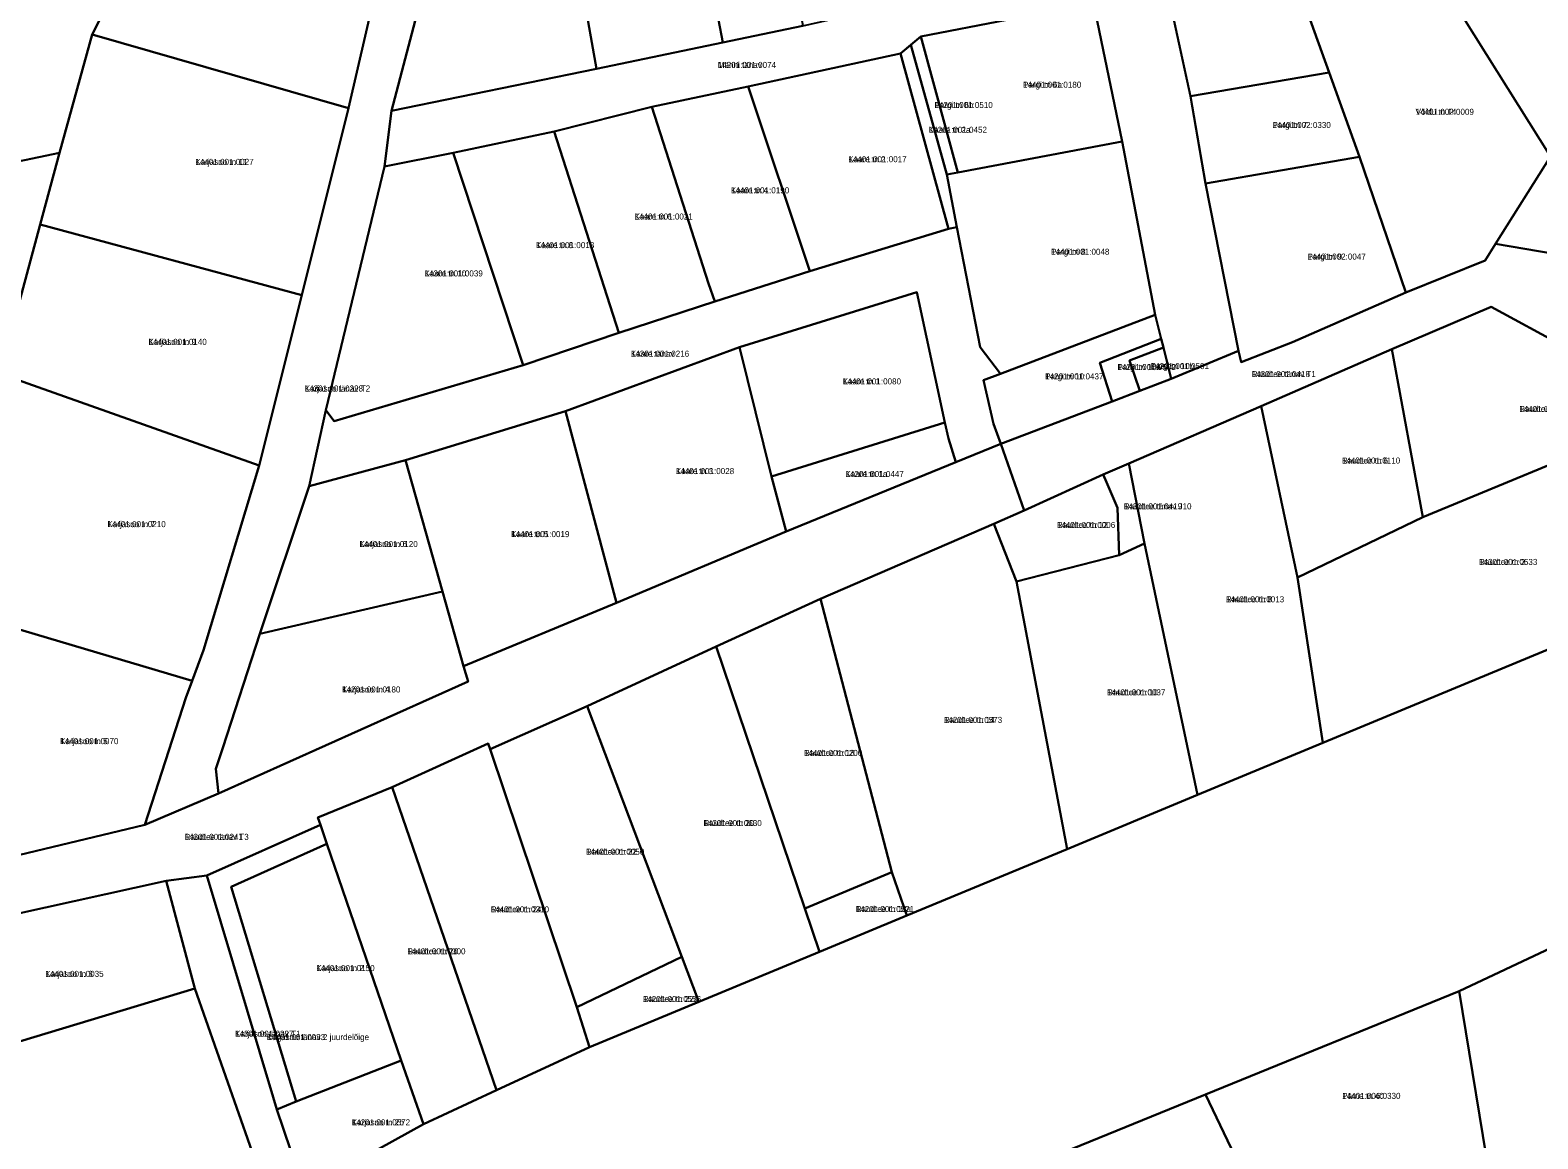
# Model space of a CAD drawing. Extents: x 640657 to 665127, y 6395726 to 6426831.
# Drawn here: x 649552.6 to 649927.6, y 6412104.6 to 6412380.5 of the extents above; entities that cross this region are included whole.
import ezdxf

# ---------------------------------------------------------------- set-up
doc = ezdxf.new("R2010")
doc.units = 0
for name, color, linetype in [('L_AADRESS', 7, 'Continuous'), ('PIIR', 7, 'Continuous'), ('TUNNUS', 7, 'Continuous')]:
    doc.layers.add(name, color=color, linetype=linetype)

msp = doc.modelspace()

# ---------------------------------------------------------------- linework, layer by layer
at = {"layer": 'PIIR'}
for points in [[(649721.82, 6412664.46), (649730.85, 6412627.05), (649736.82, 6412597.75), (649709.02, 6412592.28), (649695.48, 6412590.41), (649677.65, 6412523.96), (649682.12, 6412521.81), (649674.69, 6412506.86), (649582.66, 6412520.01), (649581.58, 6412512.13), (649530.93, 6412519.33), (649565.2, 6412417.51), (649589.31, 6412421.53), (649648.34, 6412432.29), (649646.56, 6412424.89), (649585.01, 6412412.96), (649583.88, 6412410.73), (649568.03, 6412379.35), (649559.94, 6412349.89), (649537.28, 6412345.21)], [(649834.26, 6412395.72), (649841.16, 6412363.98), (649844.88, 6412342.3), (649853.1, 6412300.7), (649836.4, 6412293.7), (649834.44, 6412301.51), (649833.89, 6412303.67), (649832.4, 6412309.6), (649824.2, 6412352.76), (649817.07, 6412387.2)], [(649931.6, 6412324.8), (649917, 6412327.3), (649930.7, 6412349)], [(649952.59, 6412291.69), (649915.96, 6412311.64), (649891.28, 6412301.06), (649858.71, 6412286.93), (649825.86, 6412272.62), (649819.47, 6412269.89), (649799.77, 6412260.97), (649794, 6412277.5), (649821.67, 6412288.07), (649828.58, 6412290.71), (649836.4, 6412293.7), (649853.1, 6412300.7), (649853.8, 6412297.8), (649866.5, 6412302.8), (649894.69, 6412315.18), (649914.43, 6412323.17), (649917, 6412327.3), (649931.6, 6412324.8)], [(649528.9, 6412170.2), (649581.09, 6412182.7), (649599.46, 6412190.55), (649661.5, 6412218.4), (649660.39, 6412222.19), (649698.42, 6412237.99), (649740.6, 6412255.75), (649782.79, 6412272.93), (649794, 6412277.5), (649799.77, 6412260.97), (649792.3, 6412257.59), (649749.16, 6412238.95), (649723.21, 6412227.12), (649691.16, 6412212.27), (649666.97, 6412201.57), (649666.5, 6412202.96), (649642.62, 6412192.14), (649624.18, 6412184.53), (649624.78, 6412182.75), (649596.55, 6412170.1), (649586.4, 6412168.82), (649518.44, 6412153.81)], [(649378.03, 6411957.6), (649560.17, 6412058.25), (649612.7, 6412087.46), (649620.75, 6412091.85), (649650.44, 6412108.25), (649668.58, 6412116.67), (649691.67, 6412127.38), (649718.88, 6412138.69), (649748.94, 6412151.16), (649770.59, 6412160.14), (649810.5, 6412176.7), (649842.91, 6412190.15), (649874.08, 6412203.09), (649950.67, 6412234.89)], [(649966.63, 6412168.97), (649907.99, 6412141.34), (649844.88, 6412115.63), (649769.67, 6412084.97), (649735.24, 6412070.53), (649620.31, 6412010.25), (649606.21, 6412000.36), (649592.49, 6411990.94), (649584.81, 6411986.06), (649559.96, 6411970.08), (649540.51, 6411961.7)]]:
    msp.add_lwpolyline(points, dxfattribs=at)
for points in [[(649744.78, 6412381.55), (649724.89, 6412377.34), (649721.61, 6412394.38), (649719.48, 6412403.99), (649714.06, 6412430.6), (649712.65, 6412437.7), (649712.08, 6412439.62), (649701.28, 6412476.03), (649725.11, 6412479.68), (649733.64, 6412439.3), (649739.77, 6412409.28)], [(649683.72, 6412425.67), (649714.06, 6412430.6), (649719.48, 6412403.99), (649721.61, 6412394.38), (649724.89, 6412377.34), (649693.47, 6412370.82)], [(649599.46, 6412190.55), (649581.09, 6412182.7), (649591.31, 6412214.32), (649592.88, 6412218.54), (649595.75, 6412226.18), (649609.52, 6412272.16), (649620.19, 6412314.5), (649631.74, 6412361.02), (649646.56, 6412424.89), (649660.68, 6412427.63), (649658.51, 6412421.66), (649642.44, 6412360.34), (649640.7, 6412346.54), (649626.17, 6412285.93), (649621.96, 6412267), (649609.71, 6412230.22), (649600.49, 6412201.9), (649598.79, 6412196.69)], [(649568.03, 6412379.35), (649583.88, 6412410.73), (649585.01, 6412412.96), (649646.56, 6412424.89), (649631.74, 6412361.02)], [(649658.51, 6412421.66), (649683.72, 6412425.67), (649693.47, 6412370.82), (649642.44, 6412360.34)], [(649901.45, 6412413.33), (649911.24, 6412406.94), (649952.6, 6412382.3), (649930.7, 6412349), (649895.82, 6412404.71)], [(649930.7, 6412349), (649917, 6412327.3), (649914.43, 6412323.17), (649894.69, 6412315.18), (649883.22, 6412348.91), (649875.65, 6412369.9), (649863.6, 6412403.34), (649892.26, 6412410.82), (649895.82, 6412404.71)], [(649834.26, 6412395.72), (649863.6, 6412403.34), (649875.65, 6412369.9), (649841.15, 6412363.99)], [(649642.44, 6412360.34), (649693.47, 6412370.82), (649724.89, 6412377.34), (649744.78, 6412381.55), (649767.83, 6412386.75), (649791.8, 6412390.86), (649815.85, 6412395.56), (649817.07, 6412387.2), (649774.12, 6412378.85), (649769.02, 6412374.6), (649731.18, 6412366.4), (649707.22, 6412361.37), (649682.96, 6412355.22), (649657.78, 6412349.92), (649640.7, 6412346.54)], [(649774.12, 6412378.85), (649817.07, 6412387.2), (649824.2, 6412352.76), (649783.35, 6412345.04)], [(649620.19, 6412314.5), (649555.12, 6412332.13), (649559.94, 6412349.89), (649568.03, 6412379.35), (649631.74, 6412361.02)], [(649771.66, 6412376.8), (649774.12, 6412378.85), (649783.35, 6412345.04), (649780.6, 6412344.5)], [(649769.02, 6412374.6), (649780.98, 6412330.98), (649746.53, 6412320.48), (649731.18, 6412366.4)], [(649780.98, 6412330.98), (649769.02, 6412374.6), (649771.66, 6412376.8), (649780.6, 6412344.5), (649783.1, 6412331.4)], [(649841.15, 6412363.99), (649875.65, 6412369.9), (649883.22, 6412348.91), (649844.88, 6412342.3)], [(649721.29, 6412317.41), (649707.22, 6412361.37), (649731.18, 6412366.4), (649746.53, 6412320.48), (649722.86, 6412312.91)], [(649682.96, 6412355.22), (649707.22, 6412361.37), (649721.29, 6412317.41), (649722.86, 6412312.91), (649698.99, 6412305.1)], [(649698.99, 6412305.1), (649675.18, 6412297.08), (649657.78, 6412349.92), (649682.96, 6412355.22)], [(649780.6, 6412344.5), (649783.35, 6412345.04), (649824.2, 6412352.76), (649832.4, 6412309.6), (649793.9, 6412294.9), (649788.9, 6412301.6), (649783.1, 6412331.4)], [(649502.69, 6412177.63), (649514.82, 6412175.76), (649522.99, 6412247.98), (649537.28, 6412345.21), (649559.94, 6412349.89), (649555.12, 6412332.13), (649545.05, 6412295.05), (649539.3, 6412261.3), (649537.33, 6412245.72), (649536.16, 6412235.4), (649528.9, 6412170.2), (649501.19, 6412163.13), (649502.36, 6412173.21)], [(649640.7, 6412346.54), (649657.78, 6412349.92), (649675.18, 6412297.08), (649628.25, 6412283.17), (649626.17, 6412285.93)], [(649844.88, 6412342.3), (649883.22, 6412348.91), (649894.69, 6412315.18), (649866.5, 6412302.8), (649853.8, 6412297.8), (649853.1, 6412300.7)], [(649620.19, 6412314.5), (649609.52, 6412272.16), (649552.04, 6412292.57), (649545.05, 6412295.05), (649555.12, 6412332.13)], [(649794, 6412277.5), (649782.79, 6412272.93), (649780.96, 6412278.85), (649780.11, 6412282.79), (649773.12, 6412315.23), (649729.05, 6412301.6), (649685.78, 6412285.67), (649645.99, 6412273.49), (649621.96, 6412267), (649626.17, 6412285.93), (649628.25, 6412283.17), (649675.18, 6412297.08), (649698.99, 6412305.1), (649722.86, 6412312.91), (649746.53, 6412320.48), (649780.98, 6412330.98), (649783.1, 6412331.4), (649788.9, 6412301.6), (649793.9, 6412294.9), (649789.7, 6412293.4), (649792.2, 6412282.5)], [(649780.11, 6412282.79), (649736.93, 6412269.39), (649729.05, 6412301.6), (649773.12, 6412315.23)], [(649891.28, 6412301.06), (649915.96, 6412311.64), (649952.59, 6412291.69), (649951.07, 6412280.86), (649898.94, 6412259.26)], [(649821.67, 6412288.07), (649794, 6412277.5), (649792.2, 6412282.5), (649789.7, 6412293.4), (649793.9, 6412294.9), (649832.4, 6412309.6), (649833.89, 6412303.67), (649818.6, 6412297.67)], [(649828.58, 6412290.71), (649821.67, 6412288.07), (649818.6, 6412297.67), (649833.89, 6412303.67), (649834.44, 6412301.51), (649826.01, 6412298.28)], [(649685.78, 6412285.67), (649729.05, 6412301.6), (649736.93, 6412269.39), (649740.6, 6412255.75), (649698.42, 6412237.99)], [(649836.4, 6412293.7), (649828.58, 6412290.71), (649826.01, 6412298.28), (649834.44, 6412301.51)], [(649858.71, 6412286.93), (649891.28, 6412301.06), (649898.94, 6412259.26), (649867.77, 6412244.26)], [(649537.33, 6412245.72), (649539.3, 6412261.3), (649545.05, 6412295.05), (649552.04, 6412292.57), (649609.52, 6412272.16), (649595.75, 6412226.18), (649592.88, 6412218.54), (649536.16, 6412235.4)], [(649951.07, 6412280.86), (649952.59, 6412291.69), (649954.77, 6412290.58), (649950.67, 6412234.89), (649874.08, 6412203.09), (649867.77, 6412244.26), (649898.94, 6412259.26)], [(649645.99, 6412273.49), (649685.78, 6412285.67), (649698.42, 6412237.99), (649660.39, 6412222.19), (649655.18, 6412240.76)], [(649858.71, 6412286.93), (649867.77, 6412244.26), (649874.08, 6412203.09), (649842.91, 6412190.15), (649829.72, 6412252.69), (649825.86, 6412272.62)], [(649782.79, 6412272.93), (649740.6, 6412255.75), (649736.93, 6412269.39), (649780.11, 6412282.79), (649780.96, 6412278.85)], [(649655.18, 6412240.76), (649609.71, 6412230.22), (649621.96, 6412267), (649645.99, 6412273.49)], [(649819.47, 6412269.89), (649825.86, 6412272.62), (649829.72, 6412252.69), (649823.45, 6412249.85), (649823.02, 6412261.61), (649820.28, 6412267.99)], [(649819.47, 6412269.89), (649820.28, 6412267.99), (649823.02, 6412261.61), (649823.45, 6412249.85), (649797.93, 6412243.29), (649792.3, 6412257.59), (649799.77, 6412260.97)], [(649810.5, 6412176.7), (649770.59, 6412160.14), (649766.87, 6412170.93), (649749.16, 6412238.95), (649792.3, 6412257.59), (649797.93, 6412243.29)], [(649829.72, 6412252.69), (649842.91, 6412190.15), (649810.5, 6412176.7), (649797.93, 6412243.29), (649823.45, 6412249.85)], [(649609.71, 6412230.22), (649655.18, 6412240.76), (649660.39, 6412222.19), (649661.5, 6412218.4), (649599.46, 6412190.55), (649598.79, 6412196.69), (649600.49, 6412201.9)], [(649745.29, 6412161.93), (649723.21, 6412227.12), (649749.16, 6412238.95), (649766.87, 6412170.93)], [(649581.09, 6412182.7), (649528.9, 6412170.2), (649536.16, 6412235.4), (649592.88, 6412218.54), (649591.31, 6412214.32)], [(649714.69, 6412149.9), (649691.16, 6412212.27), (649723.21, 6412227.12), (649745.29, 6412161.93), (649748.94, 6412151.16), (649718.88, 6412138.69)], [(649691.16, 6412212.27), (649714.69, 6412149.9), (649688.58, 6412137.38), (649666.97, 6412201.57)], [(649668.58, 6412116.67), (649642.62, 6412192.14), (649666.5, 6412202.96), (649666.97, 6412201.57), (649688.58, 6412137.38), (649691.67, 6412127.38)], [(649642.62, 6412192.14), (649668.58, 6412116.67), (649650.44, 6412108.25), (649644.9, 6412124.06), (649626.37, 6412178.02), (649624.78, 6412182.75), (649624.18, 6412184.53)], [(649596.55, 6412170.1), (649624.78, 6412182.75), (649626.37, 6412178.02), (649602.63, 6412167.34), (649618.8, 6412113.87), (649613.92, 6412111.92), (649613.03, 6412114.94)], [(649618.8, 6412113.87), (649602.63, 6412167.34), (649626.37, 6412178.02), (649644.9, 6412124.06)], [(649518.44, 6412153.81), (649586.4, 6412168.82), (649593.55, 6412141.97), (649524.06, 6412120.99)], [(649593.55, 6412141.97), (649586.4, 6412168.82), (649596.55, 6412170.1), (649613.03, 6412114.94), (649613.92, 6412111.92), (649620.75, 6412091.85), (649612.7, 6412087.46)], [(649748.94, 6412151.16), (649745.29, 6412161.93), (649766.87, 6412170.93), (649770.59, 6412160.14)], [(649907.99, 6412141.34), (649966.63, 6412168.97), (649944.74, 6412088.85), (649916.39, 6412090.28)], [(649718.88, 6412138.69), (649691.67, 6412127.38), (649688.58, 6412137.38), (649714.69, 6412149.9)], [(649524.06, 6412120.99), (649593.55, 6412141.97), (649612.7, 6412087.46), (649560.17, 6412058.25), (649535.55, 6412098.81)], [(649844.88, 6412115.63), (649907.99, 6412141.34), (649916.39, 6412090.28), (649914.19, 6412087.74), (649882.56, 6412088.24), (649857.79, 6412088.79)], [(649650.44, 6412108.25), (649620.75, 6412091.85), (649613.92, 6412111.92), (649618.8, 6412113.87), (649644.9, 6412124.06)], [(649769.67, 6412084.97), (649844.88, 6412115.63), (649857.79, 6412088.79), (649880.01, 6412042.47), (649845.57, 6412026.66), (649834.75, 6412058.52), (649790.94, 6412038.61)]]:
    msp.add_lwpolyline(points, close=True, dxfattribs=at)

# ---------------------------------------------------------------- texts
at = {"layer": 'L_AADRESS'}
for s, p in [('Männi tänav', (649723.61, 6412371.05)), ('Pargi tn 6a', (649799.51, 6412366.12)), ('Pargi tn 6b', (649777.5, 6412361.07)), ('Võidu tn 14', (649897.15, 6412359.38)), ('Kaare tn 2a', (649776.06, 6412354.91)), ('Pargi tn 7', (649861.57, 6412356.1)), ('Karjasoo tn 11', (649593.69, 6412346.93)), ('Kaare tn 2', (649756.08, 6412347.59)), ('Kaare tn 4', (649726.88, 6412339.85)), ('Kaare tn 6', (649702.91, 6412333.33)), ('Kaare tn 8', (649678.39, 6412326.21)), ('Pargi tn 8', (649806.5, 6412324.56)), ('Pargi tn 9', (649870.27, 6412323.36)), ('Kaare tn 10', (649650.68, 6412319.17)), ('Karjasoo tn 9', (649582.03, 6412302.15)), ('Kaare tänav', (649702, 6412299.2)), ('Pargi tn 10', (649805.02, 6412293.55)), ('Pargi tn 10a', (649823, 6412295.87)), ('Pargi tn 10b', (649831.27, 6412296.11)), ('Raudtee tänav T1', (649856.38, 6412294.13)), ('Karjasoo tänav T2', (649620.89, 6412290.54)), ('Kaare tn 1', (649754.69, 6412292.31)), ('Raudtee tn 4', (649922.93, 6412285.45)), ('Raudtee tn 6', (649878.82, 6412272.62)), ('Kaare tn 3', (649713.19, 6412269.99)), ('Kaare tn 1a', (649755.38, 6412269.27)), ('Raudtee tänav J10', (649824.59, 6412261.22)), ('Karjasoo tn 7', (649571.82, 6412256.79)), ('Raudtee tn 12', (649807.95, 6412256.59)), ('Kaare tn 5', (649672.21, 6412254.31)), ('Karjasoo tn 6', (649634.49, 6412251.85)), ('Raudtee tn 2', (649912.93, 6412247.39)), ('Raudtee tn 8', (649849.97, 6412238.1)), ('Karjasoo tn 4', (649630.18, 6412215.66)), ('Raudtee tn 10', (649820.42, 6412214.94)), ('Raudtee tn 14', (649779.83, 6412208.09)), ('Karjasoo tn 5', (649560.06, 6412202.8)), ('Raudtee tn 18', (649745.04, 6412199.87)), ('Raudtee tn 20', (649720.05, 6412182.42)), ('Raudtee tänav T3', (649591.01, 6412178.99)), ('Raudtee tn 22', (649690.83, 6412175.29)), ('Raudtee tn 24', (649667.14, 6412160.95)), ('Raudtee tn 18a', (649757.93, 6412161.04)), ('Raudtee tn 26', (649646.38, 6412150.52)), ('Karjasoo tn 3', (649556.37, 6412144.9)), ('Karjasoo tn 2', (649623.77, 6412146.33)), ('Raudtee tn 22a', (649704.98, 6412138.64)), ('Karjasoo tänav T1', (649603.57, 6412130.01)), ('Karjasoo tänav 2 juurdelõige', (649611.46, 6412129.17)), ('Pärna tn 40', (649878.9, 6412114.54)), ('Karjasoo tn 2b', (649632.59, 6412107.96))]:
    msp.add_text(s, height=1.5, dxfattribs=at).set_placement(p)
at = {"layer": 'TUNNUS'}
for s, p in [('14201:001:0074', (649723.61, 6412371.05)), ('14401:001:0180', (649799.51, 6412366.12)), ('14201:001:0510', (649777.5, 6412361.07)), ('14401:002:0009', (649897.15, 6412359.38)), ('14201:001:0452', (649776.06, 6412354.91)), ('14401:002:0330', (649861.57, 6412356.1)), ('14401:001:0027', (649593.69, 6412346.93)), ('14401:001:0017', (649756.08, 6412347.59)), ('14401:001:0190', (649726.88, 6412339.85)), ('14401:001:0021', (649702.91, 6412333.33)), ('14401:001:0018', (649678.39, 6412326.21)), ('14401:001:0048', (649806.5, 6412324.56)), ('14401:002:0047', (649870.27, 6412323.36)), ('14301:001:0039', (649650.68, 6412319.17)), ('14401:001:0140', (649582.03, 6412302.15)), ('14301:001:0216', (649702, 6412299.2)), ('14201:001:0437', (649805.02, 6412293.55)), ('14201:001:0502', (649823, 6412295.87)), ('14201:001:0501', (649831.27, 6412296.11)), ('14301:001:0418', (649856.38, 6412294.13)), ('14301:001:0228', (649620.89, 6412290.54)), ('14401:001:0080', (649754.69, 6412292.31)), ('14401:001:0010', (649922.93, 6412285.45)), ('14401:001:0110', (649878.82, 6412272.62)), ('14401:001:0028', (649713.19, 6412269.99)), ('14201:001:0447', (649755.38, 6412269.27)), ('14301:001:0419', (649824.59, 6412261.22)), ('14401:001:0210', (649571.82, 6412256.79)), ('14401:001:0006', (649807.95, 6412256.59)), ('14401:001:0019', (649672.21, 6412254.31)), ('14401:001:0120', (649634.49, 6412251.85)), ('14301:001:0633', (649912.93, 6412247.39)), ('14401:001:0013', (649849.97, 6412238.1)), ('14201:001:0180', (649630.18, 6412215.66)), ('14401:001:0037', (649820.42, 6412214.94)), ('14201:001:0573', (649779.83, 6412208.09)), ('14401:001:0070', (649560.06, 6412202.8)), ('14401:001:0200', (649745.04, 6412199.87)), ('14301:001:0630', (649720.05, 6412182.42)), ('14301:001:0241', (649591.01, 6412178.99)), ('14401:001:0050', (649690.83, 6412175.29)), ('14401:001:0310', (649667.14, 6412160.95)), ('14201:001:0521', (649757.93, 6412161.04)), ('14401:001:0300', (649646.38, 6412150.52)), ('14401:001:0035', (649556.37, 6412144.9)), ('14401:001:0150', (649623.77, 6412146.33)), ('14201:001:0556', (649704.98, 6412138.64)), ('14301:001:0227', (649603.57, 6412130.01)), ('14401:001:0033', (649611.46, 6412129.17)), ('14401:006:0330', (649878.9, 6412114.54)), ('14201:001:0572', (649632.59, 6412107.96))]:
    msp.add_text(s, height=1.5, dxfattribs=at).set_placement(p)

doc.saveas('drawing.dxf')
